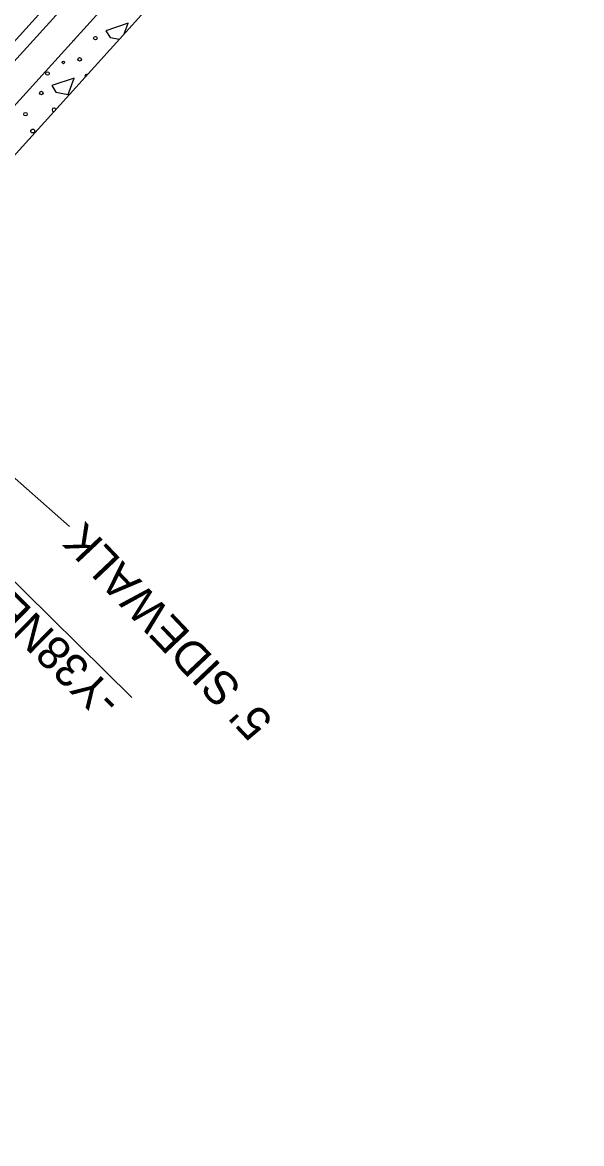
# Model space of a CAD drawing. Extents: x 1262642 to 1268358, y 767825 to 773481.
# Drawn here: x 1266954.7 to 1267038.7, y 772160.2 to 772328.8 of the extents above; entities that cross this region are included whole.
import ezdxf

# ---------------------------------------------------------------- set-up
doc = ezdxf.new("R2010")
doc.units = 0
for name, color, linetype in [('Prop Conc 2ft 6in Curb and Gutter', 7, 'Continuous'), ('Prop Conc 4in Sidewalk', 7, 'Continuous'), ('Prop Dimension Text', 7, 'Continuous'), ('Prop EOT', 7, 'Continuous'), ('Prop Horizontal Alignment', 7, 'Continuous'), ('Prop Lane Lines', 7, 'Continuous')]:
    doc.layers.add(name, color=color, linetype=linetype)

msp = doc.modelspace()

# ---------------------------------------------------------------- linework, layer by layer
at = {"layer": 'Prop Conc 2ft 6in Curb and Gutter'}
for p, q in [((1267174.15, 772567.2), (1266880.18, 772241.82)), ((1266883.52, 772238.8), (1267177.49, 772564.18)), ((1267181.29, 772560.93), (1266887.23, 772235.45)), ((1266970.6, 772328.67), (1266967.23, 772327.53)), ((1266970.01, 772327.07), (1266970.6, 772328.67)), ((1266967.23, 772327.53), (1266967.88, 772326.54)), ((1266962.4, 772325.94), (1266962.35, 772326.05)), ((1266962.54, 772326.26), (1266962.4, 772325.94)), ((1266967.88, 772326.54), (1266969.27, 772326.25)), ((1266962.48, 772320.42), (1266959.11, 772319.29)), ((1266961.56, 772317.92), (1266962.48, 772320.42)), ((1266959.11, 772319.29), (1266959.75, 772318.3)), ((1266959.75, 772318.3), (1266961.56, 772317.92))]:
    msp.add_line(p, q, dxfattribs=at)
for centre, radius in [((1266965.67, 772326.41), 0.268), ((1266960.86, 772322.76), 0.18), ((1266963.3, 772323.23), 0.268), ((1266958.47, 772321.1), 0.268), ((1266957.55, 772318.17), 0.268), ((1266955.17, 772314.99), 0.268), ((1266956.25, 772312.45), 0.285)]:
    msp.add_circle(centre, radius, dxfattribs=at)
for centre, radius, start, end in [((1266964.38, 772320.69), 0.285, 67.3561, 208.4515), ((1266959.45, 772315.62), 0.292, 15.5045, 260.3032)]:
    msp.add_arc(centre, radius, start, end, dxfattribs=at)
at = {"layer": 'Prop Conc 4in Sidewalk'}
for p, q in [((1267177.49, 772564.18), (1266883.52, 772238.8)), ((1267181.2, 772560.83), (1266887.23, 772235.45))]:
    msp.add_line(p, q, dxfattribs=at)
at = {"layer": 'Prop Dimension Text'}
for p, q in [((1266961.77, 772252.97), (1266929.06, 772281.74)), ((1266927.82, 772269.99), (1266971.15, 772227.3))]:
    msp.add_line(p, q, dxfattribs=at)
at = {"layer": 'Prop EOT'}
msp.add_line((1267172.67, 772568.54), (1266878.7, 772243.16), dxfattribs=at)
at = {"layer": 'Prop Horizontal Alignment'}
msp.add_arc((1275047.31, 780021.23), 11400, 222.993587, 225.404319, dxfattribs=at)
at = {"layer": 'Prop Lane Lines'}
msp.add_arc((1275047.31, 780021.23), 11427, 222.993587, 225.36373, dxfattribs=at)

# ---------------------------------------------------------------- texts
at = {"layer": 'Prop Dimension Text'}
for s, rotation, p in [('-Y38NE- +03.82', 135.4239, (1266969.88, 772227.15)), ("5' SIDEWALK", 133.4955, (1266992.56, 772223.84))]:
    msp.add_text(s, height=5, rotation=rotation, dxfattribs=at).set_placement(p)

doc.saveas('drawing.dxf')
